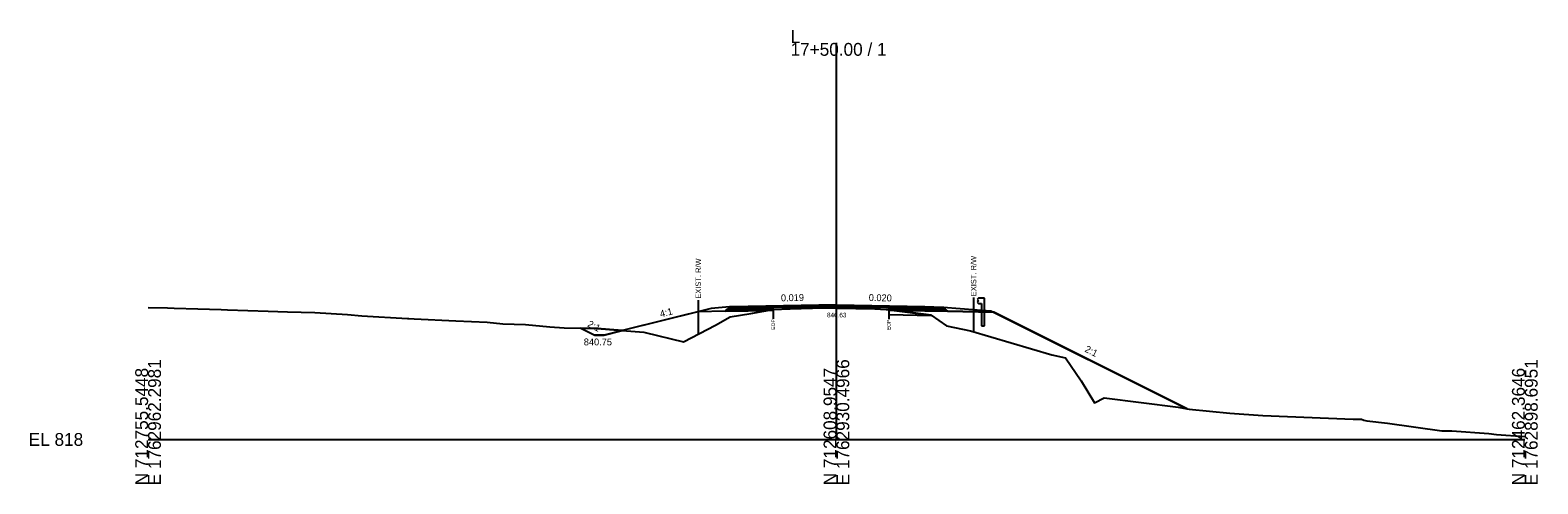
# Model space of a CAD drawing. Extents: x -26 to 5303, y -10 to 9578.
# Drawn here: x -25.7 to 302.8, y 7490.3 to 7589.3 of the extents above; entities that cross this region are included whole.
import ezdxf

# ---------------------------------------------------------------- set-up
doc = ezdxf.new("R2010")
doc.units = 0
for name, color, linetype in [('Default', 7, 'Continuous'), ('Exist CMT Pavement', 7, 'Continuous'), ('Exist Cross Section Cell', 7, 'Continuous'), ('Exist XS Ground Line', 7, 'Continuous'), ('Old_Level_10', 7, 'Continuous'), ('Old_Level_3', 7, 'Continuous'), ('Prop CMT Guardrail Graphics', 7, 'Continuous'), ('Prop CMT Pvmt Course 1', 7, 'Continuous'), ('Prop CMT Pvmt Course 2', 7, 'Continuous'), ('Prop CMT Pvmt Course 3', 7, 'Continuous'), ('Prop CMT Pvmt Surface', 7, 'Continuous'), ('Prop CMT Pvmt Surface Shoulder', 7, 'Continuous'), ('Prop CMT Shld Paved Course 1', 7, 'Continuous'), ('Prop CMT Shld Paved Course 2', 7, 'Continuous'), ('Prop CMT Shld Paved Course 3', 7, 'Continuous'), ('Prop CMT Slope Grass', 7, 'Continuous'), ('Prop CMT Subgrade Earthwork', 7, 'Continuous'), ('Prop Shade Light', 7, 'Continuous'), ('Prop XS DDE', 7, 'Continuous'), ('Prop XS DDE Earthwork Shape', 7, 'Continuous'), ('Prop XS Earthwork Shape', 7, 'Continuous'), ('Prop XS Hydro Slope Text', 7, 'Continuous'), ('Prop XS SE Text', 7, 'Continuous'), ('Prop XS Side Slope Text', 7, 'Continuous'), ('Prop XS Wedging', 7, 'Continuous')]:
    doc.layers.add(name, color=color, linetype=linetype)

msp = doc.modelspace()

# ---------------------------------------------------------------- linework, layer by layer
at = {"layer": 'Exist CMT Pavement'}
msp.add_lwpolyline([(136.2, 7528.37), (139.94, 7528.48), (147.16, 7528.68), (150, 7528.62), (158.34, 7528.48), (160.87, 7528.32), (161.4, 7528.29)], dxfattribs=at)
at = {"layer": 'Exist Cross Section Cell'}
for p, q in [((150, 7500), (150, 7586.47)), ((0, 7500), (150, 7500)), ((150, 7500), (300, 7500))]:
    msp.add_line(p, q, dxfattribs=at)
at = {"layer": 'Exist XS Ground Line'}
msp.add_lwpolyline([(0, 7528.79), (4.24, 7528.68), (5.67, 7528.66), (10.84, 7528.46), (15.91, 7528.33), (17.31, 7528.27), (26.14, 7528), (30.38, 7527.82), (36.37, 7527.69), (43.45, 7527.22), (46.6, 7526.94), (56.51, 7526.38), (56.84, 7526.37), (58.01, 7526.31), (67.07, 7525.89), (73.86, 7525.54), (77.3, 7525.21), (82.27, 7525.1), (87.53, 7524.59), (90.68, 7524.37), (97.77, 7524.2), (105.17, 7523.61), (108, 7523.41), (108.31, 7523.33), (116.65, 7521.29), (123.64, 7524.94), (126.82, 7526.77), (131.32, 7527.49), (136.19, 7528.37), (139.94, 7528.48), (147.16, 7528.68), (150, 7528.62), (158.34, 7528.48), (160.87, 7528.32), (161.4, 7528.29), (170.63, 7527.12), (174, 7524.74), (179.24, 7523.72), (196.9, 7518.48), (199.9, 7517.79), (203.31, 7512.8), (206.24, 7507.95), (208.34, 7509.06), (224.46, 7507.01), (226.88, 7506.58), (235.69, 7505.73), (242.9, 7505.22), (262.57, 7504.4), (264.39, 7504.39), (264.9, 7504.2), (265.56, 7504.09), (270.08, 7503.54), (281.95, 7501.89), (284.07, 7501.9), (292.19, 7501.26), (293.85, 7501.1), (300, 7500.62)], dxfattribs=at)
at = {"layer": 'Old_Level_10'}
for p, q in [((119.89, 7530.39), (119.89, 7522.98)), ((179.89, 7530.93), (179.89, 7523.53)), ((136.2, 7528.37), (136.2, 7526.32)), ((161.4, 7528.29), (161.4, 7526.24))]:
    msp.add_line(p, q, dxfattribs=at)
at = {"layer": 'Prop CMT Guardrail Graphics'}
for points in [[(182.27, 7530.79), (180.94, 7530.79), (180.67, 7530.49)], [(180.67, 7530.49), (180.94, 7530.2)], [(180.94, 7530.2), (180.67, 7529.91)], [(182.27, 7524.79), (182.27, 7530.79)], [(180.67, 7529.91), (180.94, 7529.62), (181.6, 7529.62)], [(181.6, 7529.62), (181.6, 7524.79)], [(181.6, 7524.79), (182.27, 7524.79)]]:
    msp.add_lwpolyline(points, dxfattribs=at)
at = {"layer": 'Prop CMT Pvmt Course 1'}
for points in [[(150, 7529.34), (130.73, 7528.98)], [(130.73, 7528.98), (130.73, 7528.73)], [(130.73, 7528.73), (136.19, 7528.83)], [(136.19, 7528.83), (150, 7529.09)], [(136.19, 7528.83), (136.19, 7528.83)], [(150, 7529.09), (150, 7529.34)], [(150, 7529.34), (169.27, 7528.96)], [(150, 7529.09), (150, 7529.09), (150, 7529.09)], [(161.4, 7528.86), (150, 7529.09)], [(169.27, 7528.71), (161.4, 7528.86)], [(161.4, 7528.86), (161.4, 7528.86)], [(169.27, 7528.96), (169.27, 7528.71)]]:
    msp.add_lwpolyline(points, dxfattribs=at)
at = {"layer": 'Prop CMT Pvmt Course 2'}
for points in [[(136.19, 7528.83), (130.73, 7528.73)], [(130.73, 7528.73), (130.73, 7528.4)], [(130.73, 7528.4), (136.19, 7528.5)], [(136.19, 7528.5), (136.19, 7528.83)], [(161.4, 7528.53), (161.4, 7528.86)], [(161.4, 7528.86), (169.27, 7528.71)], [(169.27, 7528.37), (161.4, 7528.53)], [(169.27, 7528.71), (169.27, 7528.37)]]:
    msp.add_lwpolyline(points, dxfattribs=at)
at = {"layer": 'Prop CMT Pvmt Course 3'}
for points in [[(136.19, 7528.5), (130.73, 7528.4)], [(130.73, 7528.4), (130.73, 7528.06)], [(130.73, 7528.06), (136.19, 7528.17)], [(136.19, 7528.17), (136.19, 7528.5)], [(161.4, 7528.53), (169.27, 7528.37)], [(161.4, 7528.2), (161.4, 7528.53)], [(169.27, 7528.04), (161.4, 7528.2)], [(169.27, 7528.37), (169.27, 7528.04)]]:
    msp.add_lwpolyline(points, dxfattribs=at)
at = {"layer": 'Prop CMT Pvmt Surface'}
for points in [[(150, 7529.34), (130.73, 7528.98)], [(150, 7529.34), (169.27, 7528.96)]]:
    msp.add_lwpolyline(points, dxfattribs=at)
at = {"layer": 'Prop CMT Pvmt Surface Shoulder'}
for points in [[(130.73, 7528.98), (126.73, 7528.9)], [(169.27, 7528.96), (173.27, 7528.88)]]:
    msp.add_lwpolyline(points, dxfattribs=at)
at = {"layer": 'Prop CMT Shld Paved Course 1'}
for points in [[(130.73, 7528.98), (126.73, 7528.9), (126.47, 7528.65)], [(126.47, 7528.65), (130.73, 7528.73)], [(130.73, 7528.73), (130.73, 7528.98)], [(169.27, 7528.96), (173.27, 7528.88), (173.53, 7528.62)], [(169.27, 7528.71), (169.27, 7528.96)], [(173.53, 7528.62), (169.27, 7528.71)]]:
    msp.add_lwpolyline(points, dxfattribs=at)
at = {"layer": 'Prop CMT Shld Paved Course 2'}
for points in [[(130.73, 7528.73), (126.47, 7528.65), (126.13, 7528.31)], [(126.13, 7528.31), (130.73, 7528.4)], [(130.73, 7528.4), (130.73, 7528.73)], [(169.27, 7528.71), (173.53, 7528.62), (173.87, 7528.28)], [(169.27, 7528.37), (169.27, 7528.71)], [(173.87, 7528.28), (169.27, 7528.37)]]:
    msp.add_lwpolyline(points, dxfattribs=at)
at = {"layer": 'Prop CMT Shld Paved Course 3'}
for points in [[(126.13, 7528.31), (125.79, 7527.97)], [(125.79, 7527.97), (130.73, 7528.06)], [(130.73, 7528.4), (126.13, 7528.31)], [(126.13, 7528.31), (126.13, 7528.31)], [(130.73, 7528.06), (130.73, 7528.4)], [(169.27, 7528.37), (173.87, 7528.28)], [(169.27, 7528.04), (169.27, 7528.37)], [(174.21, 7527.94), (169.27, 7528.04)], [(173.87, 7528.28), (173.87, 7528.28)], [(173.87, 7528.28), (174.21, 7527.94)]]:
    msp.add_lwpolyline(points, dxfattribs=at)
at = {"layer": 'Prop CMT Slope Grass'}
msp.add_line((183.67, 7528.05), (226.43, 7506.66), dxfattribs=at)
for points in [[(126.73, 7528.9), (122.73, 7528.59), (103.39, 7523.75)], [(173.27, 7528.88), (180.67, 7528.29)], [(180.67, 7528.29), (183.67, 7528.05)]]:
    msp.add_lwpolyline(points, dxfattribs=at)
at = {"layer": 'Prop CMT Subgrade Earthwork'}
for p, q in [((136.2, 7528.37), (136.19, 7528.17)), ((161.4, 7528.29), (161.4, 7528.2))]:
    msp.add_line(p, q, dxfattribs=at)
for points in [[(125.79, 7527.97), (119.8, 7527.86)], [(130.73, 7528.06), (125.79, 7527.97)], [(136.19, 7528.17), (130.73, 7528.06)], [(161.4, 7528.2), (169.27, 7528.04)], [(169.27, 7528.04), (174.21, 7527.94)], [(174.21, 7527.94), (184.28, 7527.74)]]:
    msp.add_lwpolyline(points, dxfattribs=at)
at = {"layer": 'Prop Shade Light'}
for p, q in [((162.23, 7528.18), (161.4, 7528.2)), ((161.4, 7528.2), (161.4, 7527.28)), ((161.4, 7527.28), (170.75, 7527.03)), ((170.63, 7527.12), (162.23, 7528.18)), ((170.75, 7527.03), (170.63, 7527.12))]:
    msp.add_line(p, q, dxfattribs=at)
at = {"layer": 'Prop XS DDE'}
for p, q in [((94.31, 7524.28), (97.37, 7522.75)), ((103.39, 7523.75), (99.37, 7522.75)), ((99.37, 7522.75), (97.37, 7522.75))]:
    msp.add_line(p, q, dxfattribs=at)
at = {"layer": 'Prop XS DDE Earthwork Shape'}
for p, q in [((97.77, 7524.2), (94.31, 7524.28)), ((94.31, 7524.28), (97.37, 7522.75)), ((103.39, 7523.75), (97.77, 7524.2)), ((99.37, 7522.75), (103.39, 7523.75)), ((97.37, 7522.75), (99.37, 7522.75))]:
    msp.add_line(p, q, dxfattribs=at)
msp.add_lwpolyline([(103.39, 7523.75), (103.39, 7523.75)], dxfattribs=at)
at = {"layer": 'Prop XS Earthwork Shape'}
for points in [[(105.17, 7523.61), (108, 7523.41), (108.31, 7523.33), (116.65, 7521.29), (123.64, 7524.94), (126.82, 7526.77), (131.32, 7527.49), (134.93, 7528.14), (130.73, 7528.06), (125.79, 7527.97), (119.8, 7527.86), (103.39, 7523.75)], [(136.2, 7528.37), (136.19, 7528.17), (134.93, 7528.14)], [(161.4, 7528.29), (161.4, 7528.2), (162.23, 7528.18)], [(199.9, 7517.79), (203.31, 7512.8), (206.24, 7507.95), (208.34, 7509.06), (224.46, 7507.01), (226.44, 7506.66), (226.43, 7506.66), (184.28, 7527.74), (174.21, 7527.94), (169.27, 7528.04), (162.23, 7528.18), (170.63, 7527.12), (174, 7524.74), (179.24, 7523.72), (196.9, 7518.48)]]:
    msp.add_lwpolyline(points, close=True, dxfattribs=at)
at = {"layer": 'Prop XS Wedging'}
msp.add_lwpolyline([(136.19, 7528.37), (136.19, 7528.83), (139.94, 7528.9), (147.16, 7529.04), (150, 7529.09), (158.34, 7528.93), (160.87, 7528.88), (161.4, 7528.87), (161.4, 7528.29), (160.87, 7528.32), (158.34, 7528.48), (150, 7528.62), (147.16, 7528.68), (139.94, 7528.48)], close=True, dxfattribs=at)

# ---------------------------------------------------------------- texts
at = {"layer": 'Default'}
msp.add_text('-', height=0.0001, dxfattribs=at).set_placement((0, 7500))
at = {"layer": 'Exist Cross Section Cell'}
for s, p in [('L', (140, 7586.47)), ('17+50.00 / 1', (140, 7583.67)), ('EL 818', (-26, 7498.6))]:
    msp.add_text(s, height=2.8, dxfattribs=at).set_placement(p)
for s, p in [('E 1762962.2981', (2.8, 7490)), ('E 1762930.4966', (152.8, 7490)), ('E 1762898.6951', (302.8, 7490)), ('N 712755.5448', (0, 7490)), ('N 712608.9547', (150, 7490)), ('N 712462.3646', (300, 7490))]:
    msp.add_text(s, height=2.8, rotation=90, dxfattribs=at).set_placement(p)
at = {"layer": 'Old_Level_10'}
for s, height, p in [('EXIST. R/W', 1.181, (120.48, 7530.69)), ('EXIST. R/W', 1.181, (180.48, 7531.24)), ('EOP', 0.787, (136.59, 7523.92)), ('EOP', 0.787, (161.79, 7523.84))]:
    msp.add_text(s, height=height, rotation=90, dxfattribs=at).set_placement(p)
at = {"layer": 'Old_Level_3'}
msp.add_text('846.63', height=1, dxfattribs=at).set_placement((147.95, 7526.63))
at = {"layer": 'Prop XS Hydro Slope Text'}
msp.add_text('2:1', height=1.5, rotation=333.4349, dxfattribs=at).set_placement((95.62, 7524.69))
msp.add_text('840.75', height=1.5, dxfattribs=at).set_placement((94.95, 7520.51))
at = {"layer": 'Prop XS SE Text'}
for s, rotation, p in [('0.019', 1.0779, (137.92, 7530.12)), ('0.020', 358.8542, (157.03, 7530.2))]:
    msp.add_text(s, height=1.5, rotation=rotation, dxfattribs=at).set_placement(p)
at = {"layer": 'Prop XS Side Slope Text'}
for s, rotation, p in [('4:1', 14.0362, (111.72, 7526.61)), ('2:1', 333.4349, (203.97, 7519.21))]:
    msp.add_text(s, height=1.5, rotation=rotation, dxfattribs=at).set_placement(p)

doc.saveas('drawing.dxf')
